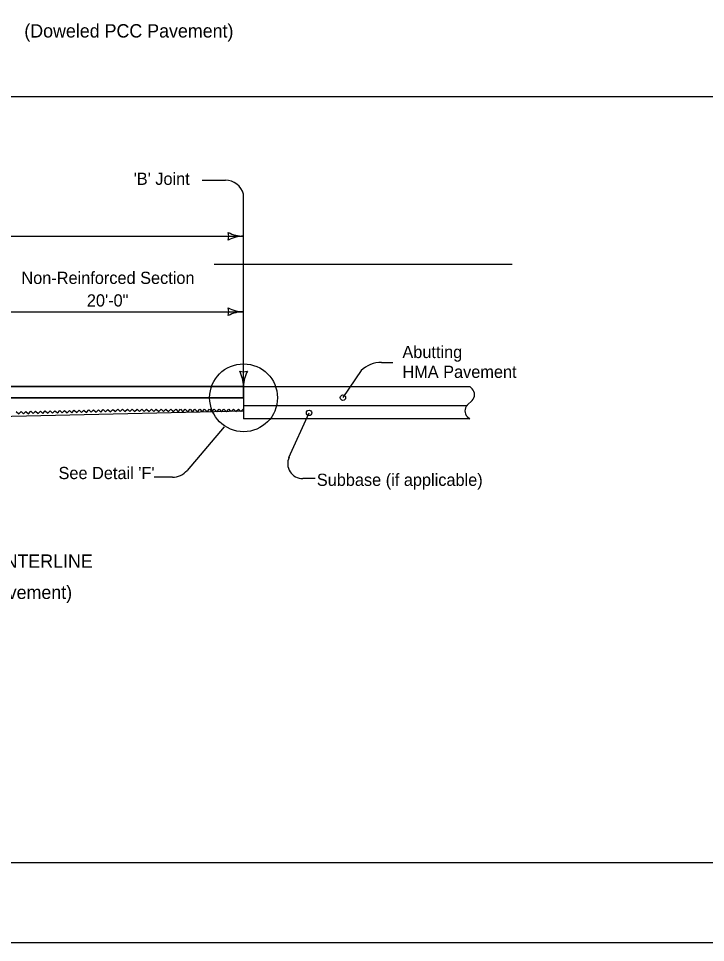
# Model space of a CAD drawing. Extents: x -2135039 to -2124495, y -2139046 to -2132546.
# Drawn here: x -2130115 to -2129213, y -2135130 to -2133919 of the extents above; entities that cross this region are included whole.
import ezdxf

# ---------------------------------------------------------------- set-up
doc = ezdxf.new("R2010")
doc.units = 0
for name, color, linetype in [('BridgeSuperStructureExisting', 7, 'Continuous'), ('dsnAlignmentCurveData', 7, 'Continuous'), ('dsnAlignmentStation', 7, 'Continuous'), ('dsnStdLabel', 7, 'Continuous'), ('dsnStdLineWork', 7, 'Continuous'), ('TC_Barrier', 7, 'Continuous')]:
    doc.layers.add(name, color=color, linetype=linetype)

msp = doc.modelspace()

# ---------------------------------------------------------------- linework, layer by layer
at = {"layer": 'BridgeSuperStructureExisting'}
for p, q in [((-2129873.6, -2134130.8), (-2129843.1, -2134130.8)), ((-2129819.2, -2134401.4), (-2129819.2, -2134149.1)), ((-2130980.5, -2134204.3), (-2129819.2, -2134204.3)), ((-2129857.8, -2134240.8), (-2129466.9, -2134240.8)), ((-2130175.6, -2134303.3), (-2129819.2, -2134303.3)), ((-2129638.1, -2134369.8), (-2129623.3, -2134369.8)), ((-2129665.1, -2134380.5), (-2129688.8, -2134416)), ((-2130977.5, -2134401.4), (-2129819.2, -2134401.4)), ((-2129819.2, -2134401.4), (-2130175.6, -2134401.4)), ((-2129819.2, -2134416.2), (-2129819.2, -2134401.4)), ((-2129819.2, -2134401.4), (-2129522.4, -2134401.4)), ((-2129819.2, -2134401.4), (-2129819.2, -2134416.2)), ((-2129537, -2134401.4), (-2129537, -2134401.4)), ((-2129519.3, -2134404.5), (-2129522.4, -2134401.4)), ((-2129819.2, -2134416.2), (-2130977.5, -2134416.2)), ((-2130175.6, -2134416.2), (-2129819.2, -2134416.2)), ((-2129819.2, -2134416.2), (-2129819.2, -2134443.9)), ((-2129525.6, -2134425.9), (-2129519.3, -2134419.6)), ((-2129819.2, -2134426.1), (-2129525.8, -2134426.1)), ((-2129819.2, -2134433.9), (-2130943.9, -2134459.3)), ((-2129522.6, -2134443.9), (-2129819.2, -2134443.9)), ((-2129759.6, -2134494.3), (-2129733.3, -2134436)), ((-2129522.4, -2134444.1), (-2129525.6, -2134441)), ((-2129844.7, -2134454.4), (-2129893.3, -2134511.5)), ((-2129912.4, -2134520.3), (-2129936.6, -2134520.3)), ((-2129725.3, -2134522.2), (-2129741.5, -2134522.2))]:
    msp.add_line(p, q, dxfattribs=at)
for points in [[(-2130117.4, -2134434.3), (-2130114.2, -2134437.4), (-2130111.1, -2134434.2), (-2130107.8, -2134437.3), (-2130104.7, -2134434), (-2130101.5, -2134437.1), (-2130098.4, -2134433.9), (-2130095.2, -2134437), (-2130092.1, -2134433.7), (-2130088.8, -2134436.8), (-2130085.7, -2134433.6), (-2130082.5, -2134436.7), (-2130079.4, -2134433.5), (-2130076.2, -2134436.5), (-2130073.1, -2134433.3), (-2130069.8, -2134436.4), (-2130066.7, -2134433.2), (-2130065.1, -2134434.7)], [(-2130065.1, -2134434.7), (-2130063.5, -2134436.2), (-2130060.4, -2134433), (-2130057.2, -2134436.1), (-2130054.1, -2134432.9), (-2130050.8, -2134435.9), (-2130047.7, -2134432.7), (-2130044.5, -2134435.8), (-2130041.4, -2134432.6), (-2130038.2, -2134435.6), (-2130035.1, -2134432.4), (-2130031.8, -2134435.5), (-2130028.7, -2134432.3), (-2130025.5, -2134435.3), (-2130022.4, -2134432.1), (-2130019.2, -2134435.2), (-2130016.1, -2134432), (-2130012.8, -2134435.1), (-2130009.7, -2134431.8), (-2130006.5, -2134434.9), (-2130003.4, -2134431.7), (-2130000.2, -2134434.8), (-2129997.1, -2134431.5), (-2129993.8, -2134434.6), (-2129990.7, -2134431.4), (-2129989.1, -2134432.9)], [(-2129989.1, -2134432.8), (-2129987.5, -2134434.4), (-2129984.4, -2134431.2), (-2129981.2, -2134434.3), (-2129978, -2134431.2), (-2129974.9, -2134434.3), (-2129971.7, -2134431.2), (-2129968.5, -2134434.3), (-2129965.4, -2134431.2), (-2129962.2, -2134434.3), (-2129959, -2134431.2), (-2129955.9, -2134434.3), (-2129952.7, -2134431.1), (-2129949.5, -2134434.3), (-2129946.4, -2134431.1), (-2129943.2, -2134434.3), (-2129940, -2134431.1), (-2129936.8, -2134434.3), (-2129933.7, -2134431.1), (-2129930.5, -2134434.3), (-2129927.3, -2134431.1), (-2129924.2, -2134434.3), (-2129921, -2134431.1), (-2129917.8, -2134434.3), (-2129914.7, -2134431.1), (-2129913.1, -2134432.7)], [(-2129913.1, -2134432.9), (-2129911.5, -2134434.5), (-2129908.3, -2134431.3), (-2129905.2, -2134434.5), (-2129902, -2134431.3), (-2129898.8, -2134434.5), (-2129895.7, -2134431.3), (-2129892.5, -2134434.5), (-2129889.3, -2134431.3), (-2129886.2, -2134434.5), (-2129883, -2134431.3), (-2129879.8, -2134434.4), (-2129876.7, -2134431.3), (-2129873.5, -2134434.4), (-2129870.3, -2134431.3), (-2129867.1, -2134434.4), (-2129864, -2134431.3), (-2129860.8, -2134434.4), (-2129857.6, -2134431.2), (-2129854.5, -2134434.4), (-2129851.3, -2134431.2), (-2129848.1, -2134434.4), (-2129845, -2134431.2), (-2129841.8, -2134434.4), (-2129838.6, -2134431.2), (-2129837.1, -2134432.8)], [(-2129837.1, -2134432.5), (-2129835.5, -2134434), (-2129832.3, -2134430.9), (-2129829.2, -2134434), (-2129826, -2134430.9), (-2129822.8, -2134434), (-2129819.7, -2134430.9), (-2129819.2, -2134431.3)]]:
    msp.add_lwpolyline(points, dxfattribs=at)
msp.add_circle((-2129819.2, -2134416.2), 44.5, dxfattribs=at)
for centre, radius, start, end in [((-2129843.1, -2134155.5), 24.7, 15.0299, 90), ((-2129855.1, -2134204.3), 16.5, 342.2666, 17.7333), ((-2129819.2, -2134161.6), 42.7, 241.9275, 270), ((-2129819.2, -2134247.1), 42.7, 90, 118.0725), ((-2129855.1, -2134303.3), 16.5, 342.2666, 17.7333), ((-2129819.2, -2134260.6), 42.7, 241.9275, 270), ((-2129819.2, -2134346.1), 42.7, 90, 118.0725), ((-2129638.1, -2134409.4), 39.6, 90, 132.998), ((-2129819.2, -2134365.5), 16.5, 252.2666, 287.7333), ((-2129862, -2134401.4), 42.7, 360, 28.0725), ((-2129776.5, -2134401.4), 42.7, 151.9275, 180), ((-2129526.9, -2134412.1), 10.7, 315, 45), ((-2129518, -2134433.4), 10.7, 135, 225), ((-2129741.5, -2134502.4), 19.8, 155.762, 270), ((-2129912.4, -2134495.3), 25, 270, 319.6052)]:
    msp.add_arc(centre, radius, start, end, dxfattribs=at)
at = {"layer": 'dsnAlignmentCurveData'}
msp.add_line((-2131334.4, -2134021), (-2128199.4, -2134021), dxfattribs=at)
at = {"layer": 'dsnAlignmentStation'}
msp.add_lwpolyline([(-2131334.4, -2133016), (-2128199.4, -2133016), (-2128199.4, -2135026), (-2131334.4, -2135026)], close=True, dxfattribs=at)
at = {"layer": 'dsnStdLineWork'}
msp.add_lwpolyline([(-2131438.9, -2135130.5), (-2128094.9, -2135130.5), (-2128094.9, -2132546.5), (-2131438.9, -2132546.5)], close=True, dxfattribs=at)
at = {"layer": 'TC_Barrier'}
for centre in [(-2129688.8, -2134416), (-2129733.3, -2134436)]:
    msp.add_circle(centre, 3.54, dxfattribs=at)

# ---------------------------------------------------------------- texts
at = {"layer": 'BridgeSuperStructureExisting'}
msp.add_text('SECTION THRU CENTERLINE', height=17.5, dxfattribs=at).set_placement((-2130347.3, -2134639.1))
at = {"layer": 'dsnStdLabel'}
for s, height, p in [('(Doweled PCC Pavement)', 17.5, (-2130106.9, -2133943.8)), ("'B' Joint", 16, (-2129963.4, -2134137)), ('Non-Reinforced Section', 16, (-2130110.7, -2134266.9)), ('20\'-0"', 16, (-2130024.8, -2134296.5)), ('Abutting', 16, (-2129610.8, -2134364.1)), ('HMA Pavement', 16, (-2129610.8, -2134390.1)), ("See Detail 'F'", 16, (-2130062, -2134522.8)), ('Subbase (if applicable)', 16, (-2129723.1, -2134531.7)), ('(Abutting HMA Pavement)', 17.5, (-2130316, -2134680))]:
    msp.add_text(s, height=height, dxfattribs=at).set_placement(p)

doc.saveas('drawing.dxf')
